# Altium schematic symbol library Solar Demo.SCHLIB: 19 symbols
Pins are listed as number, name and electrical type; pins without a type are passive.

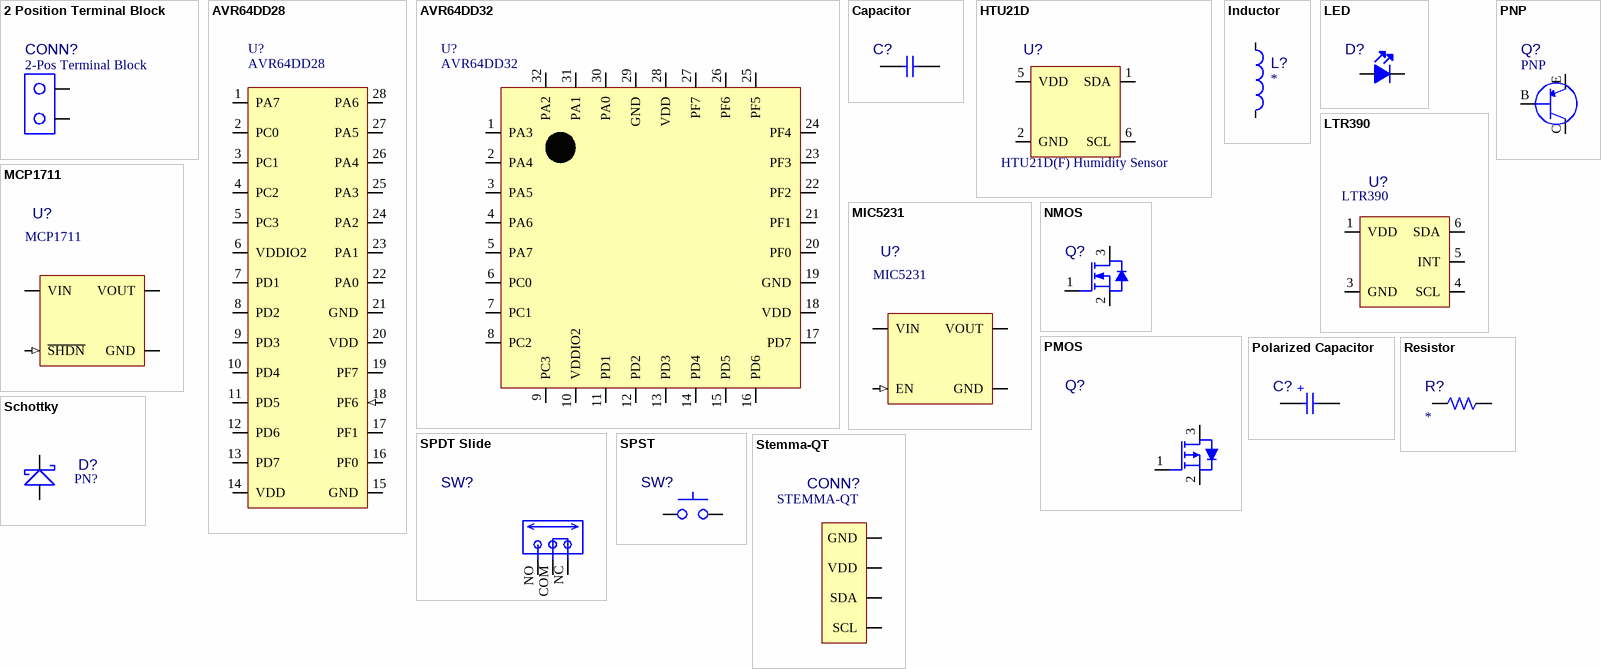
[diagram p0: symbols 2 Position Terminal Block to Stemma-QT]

## 2 Position Terminal Block
designator CONN?, comment 2-Pos Terminal Block
pins: A, B

## AVR64DD28
designator U?
pins: 1 PA7 (io), 2 PC0 (io), 3 PC1 (io), 4 PC2 (io), 5 PC3 (io), 6 VDDIO2 (power), 7 PD1 (io), 8 PD2 (io), 9 PD3 (io), 10 PD4 (io), 11 PD5 (io), 12 PD6 (io), 13 PD7 (io), 14 VDD (io), 15 GND (power), 16 PF0 (io), 17 PF1 (io), 18 PF6 (in), 19 PF7 (io), 20 VDD (power), 21 GND (power), 22 PA0 (io), 23 PA1 (io), 24 PA2 (io), 25 PA3 (io), 26 PA4 (io), 27 PA5 (io), 28 PA6 (io)

## AVR64DD32
designator U?
pins: 1 PA3 (io), 2 PA4 (io), 3 PA5 (io), 4 PA6 (io), 5 PA7 (io), 6 PC0 (io), 7 PC1 (io), 8 PC2 (io), 9 PC3 (io), 10 VDDIO2 (power), 11 PD1 (io), 12 PD2 (io), 13 PD3 (io), 14 PD4 (io), 15 PD5 (io), 16 PD6 (io), 17 PD7 (io), 18 VDD (power), 19 GND (power), 20 PF0 (io), 21 PF1 (io), 22 PF2 (io), 23 PF3 (io), 24 PF4 (io), 25 PF5 (io), 26 PF6 (io), 27 PF7 (io), 28 VDD (power), 29 GND (power), 30 PA0 (io), 31 PA1 (io), 32 PA2 (io)

## Capacitor
designator C?  (value not drawn)
pins: 1, 2

## HTU21D
designator U?, comment HTU21D(F) Humidity Sensor
pins: 1 SDA (oc), 2 GND (power), 5 VDD (power), 6 SCL (oc)

## Inductor
designator L?
pins: 1, 2

## LED
designator D?  (value not drawn)
pins: A Anode, K Cathode

## LTR390
designator U?
pins: 1 VDD (power), 3 GND (power), 4 SCL (oc), 5 INT (oc), 6 SDA (oc)

## MCP1711
designator U?
pins: 1 VIN (power), 2 GND (power), 3 ~{SHDN} (in), 5 VOUT (power)

## MIC5231
designator U?
pins: EN (in), GND (power), VIN (power), VOUT (power)

## NMOS
designator Q?, comment NMOS Transistor  (value not drawn)
pins: 1 G, 2 S, 3 D

## PMOS
designator Q?, comment PMOS Transistor  (value not drawn)
pins: 1 G, 2 S, 3 D

## PNP
designator Q?
PNP Transistor
pins: B (power), C (power), E (power)

## Polarized Capacitor
designator C?  (value not drawn)
pins: A, K

## Resistor
designator R?
pins: 1, 2

## Schottky
designator D?  Part Number: PN?  (hidden comment: *)
pins: A ANODE, K CATHODE

## SPDT Slide
designator SW?  (value not drawn)
pins: COM (power), NC (power), NO (power)

## SPST
designator SW?, comment SPST Switch  (value not drawn)
pins: 1, 2

## Stemma-QT
designator CONN?, comment STEMMA-QT
Used with JST-ST Cables
pins: 1 GND, 2 VDD, 3 SDA, 4 SCL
